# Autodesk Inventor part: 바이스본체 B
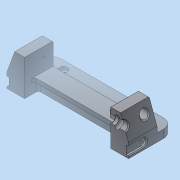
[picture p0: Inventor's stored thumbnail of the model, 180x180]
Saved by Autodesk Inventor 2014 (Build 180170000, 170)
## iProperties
Created: 2017-04
Part Number: 바이스본체 B
Material: 알루미늄 6061
Document SubType Name: Modeling
Designer: mduedu
Density: 2.71 g/cm^3
Appearance: 기본값
Mass: 324.113 g
Surface Area: 275.971 cm^2
Volume: 119.599 cm^3
Author: mduedu
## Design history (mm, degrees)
sketch "스케치1"
  geometry: L1 (-75, 0)-(75, 0); L2 (-75, 0)-(-75, 17); L3 (-53, 17)-(53, 17); L4 (75, 17)-(75, 0); L5 (-75, 17)-(-65.173, 44); L6 (-65.173, 44)-(-53, 44); L7 (-53, 44)-(-53, 17); L8 (0, 0)-(0, 17); L9 (75, 17)-(65.173, 44); L10 (65.173, 44)-(53, 44); L11 (53, 44)-(53, 17); 1 further point
  constraints: 22 end point, 4 perpendicular, 2 horizontal alignment, 2 midpoint, 2 symmetric about line, 1 coincident, 1 collinear, 1 horizontal, 1 vertical
  dimensions: "d0" = 150 distance of L1.start L1.end; "d1" = 17 distance of L1.start L2.end; "d2" = 27 distance of L3.start L6.end; "d3" = 22 distance of L3.start L2.end; "d4" = 70 deg angle of L3 L5; "d54" = 20 deg angle of L9 L4
extrude "돌출1" new body sketch "스케치1" stored distance "d5" = 70; taper "d6" = 0 deg
sketch "스케치2"
  geometry: L1 (0, 70)-(106, 70) reference; L2 (106, 70)-(106, 0) reference; L3 (106, 0)-(0, 0) reference; L4 (0, 47)-(106, 47); L5 (106, 47)-(106, 23); L6 (106, 23)-(0, 23); L7 (0, 23)-(0, 47); L8 (0, 70)-(0, 0) reference; 2 further points
  constraints: 8 end point, 2 parallel, 2 point on line, 1 horizontal, 1 horizontal alignment, 1 midpoint, 1 perpendicular
  dimensions: "d7" = 24 distance between parallel lines of L6 L4
extrude "돌출2" cut sketch "스케치2" stored distance "d9" = 70; taper "d10" = 0 deg
sketch "스케치3"
  geometry: L1 (22, -23)-(128, -23) reference; L2 (128, -47)-(22, -47) reference; L3 (22, -18)-(128, -18); L4 (128, -52)-(22, -52); L5 (22, -18)-(22, -52); L6 (128, -18)-(128, -52); 1 further point
  constraints: 8 end point, 3 parallel, 2 point on line, 1 perpendicular
  dimensions: "d11" = 5 distance between parallel lines of L3 L1; "d12" = 5 distance between parallel lines of L4 L2
extrude "돌출3" cut sketch "스케치3" distance "d13" = 12; taper "d14" = 0 deg
fillet "모깎기1" dims "d15" = 3, "d16" = 3
sketch "스케치4"
  geometry: L1 (103, 23)-(3, 23) reference; L2 (0, 26)-(0, 0) reference; L3 (106, 0)-(0, 0) reference; L4 (106, 26)-(106, 0) reference; L5 (96, 0)-(90, 0); L6 (90, 0)-(90, 19.5); L7 (96, 19.5)-(96, 0); L8 (90, 19.5)-(96, 19.5); A1 r 3 centre (3, 26) between (0, 26) and (3, 23) reference; A2 r 3 centre (103, 26) between (103, 23) and (106, 26) reference; 1 further point
  constraints: 8 end point, 2 perpendicular, 1 horizontal, 1 parallel, 1 point on line
  dimensions: "d17" = 10 distance between parallel lines of L7 L4; "d18" = 6 distance between parallel lines of L7 L6; "d27" = 3.5 distance between parallel lines of L8 L1
extrude "돌출4" join sketch "스케치4" distance "d19" = 12; taper "d20" = 0 deg
chamfer "모따기1" distance "d21" = 3; stored, may be unused: second distance "d22" = 2, angle "d23" = 45 deg
chamfer "모따기2" distance "d24" = 3; stored, may be unused: second distance "d25" = 2, angle "d26" = 45 deg
sketch "스케치5"
  geometry: L1 (-15.5, 35.8)-(-15.5, -25.8) reference; L2 (19.5, 0)-(0, 0) reference; C1 r 6.5 at (9.5, 15); 1 further point
  constraints: 1 centre point
  dimensions: "d28" = 13 diameter of C1; "d30" = 15 distance from line of C1.centre L2; "d31" = 25 distance from line of C1.centre L1
extrude "돌출5" cut sketch "스케치5" stored distance "d32" = 12; taper "d33" = 0 deg
sketch "스케치6"
  geometry: C1 r 5 at (-10, 15); C2 r 5 at (-60, 15); A1 r 6.5 centre (-10, 15) between (-15.766, 12) and (-4.234, 12) reference; A2 r 6.5 centre (-60, 15) between (-65.766, 12) and (-54.234, 12) reference; 1 further point
  constraints: 2 centre point, 2 coincident
  dimensions: "d34" = 10 diameter of C1; "d35" = 10 diameter of C2 (= d34)
extrude "돌출6" cut sketch "스케치6" stored distance "d36" = 12; taper "d37" = 0 deg
chamfer "모따기3" distance "d38" = 1; stored, may be unused: second distance "d39" = 2, angle "d40" = 45 deg
chamfer "모따기4" distance "d41" = 1; stored, may be unused: second distance "d42" = 2, angle "d43" = 45 deg
sketch "스케치7"
  geometry: L1 (-35, 35.8)-(-35, -25.8) reference; L2 (-70, 0)-(0, 0) reference; C1 r 5 at (-35, 15); 1 further point
  constraints: 1 centre point, 1 point on line
  dimensions: "d44" = 10 diameter of C1; "d45" = 15 distance from line of C1.centre L2
extrude "돌출7" cut sketch "스케치7" stored distance "d46" = 12; taper "d47" = 0 deg
chamfer "모따기5" distance "d48" = 1; stored, may be unused: second distance "d49" = 2, angle "d50" = 45 deg
node "작업축1"
sketch "스케치8"
  geometry: L1 (-105, 32)-(105, 32) reference; L2 (58, 32)-(64, 32); L3 (64, 32)-(64, 40); L4 (64, 40)-(58, 40); L5 (58, 40)-(58, 32); L6 (53, 38)-(53, 26) reference; 1 further point
  constraints: 8 end point, 2 parallel, 1 horizontal, 1 perpendicular, 1 point on line
  dimensions: "d51" = 5 distance from line of L6 L2.start; "d52" = 6 distance of L3.end L4.end; "d53" = 16 diameter of L4 L1
revolve "회전1" sketch "스케치8" stored, may be unused: angle "d55" = 90 deg
fillet "모깎기2"
chamfer "모따기6" distance "d56" = 1; stored, may be unused: second distance "d57" = 2, angle "d58" = 45 deg
sketch "스케치9"
  geometry: L1 (17.5, 3)-(52.5, 3); L2 (52.5, 13)-(17.5, 13); L3 (70, 0)-(0, 0) reference; L4 (17.5, 8)-(52.5, 8); A1 r 5 centre (17.5, 8) between (17.5, 13) and (17.5, 3); A2 r 5 centre (52.5, 8) between (52.5, 3) and (52.5, 13); 3 further points
  constraints: 6 end point, 4 point on circle, 3 tangent, 2 centre point, 2 midpoint, 2 parallel, 1 horizontal, 1 vertical alignment
  dimensions: "d59" = 35 distance of L4.start L4.end; "d61" = 5 radius of A2; "d62" = 8 distance between parallel lines of L3 L4
extrude "돌출8" cut sketch "스케치9" distance "d63" = 3; taper "d64" = 0 deg
chamfer "모따기7" distance "d65" = 1; stored, may be unused: second distance "d66" = 2, angle "d67" = 45 deg
chamfer "모따기8" distance "d68" = 1; stored, may be unused: second distance "d69" = 2, angle "d70" = 45 deg
feature "분할1"
sketch "스케치10"
  geometry: A1 r 5 centre (0, 0) between (0, 5) and (0, -5) reference; 1 further point
  constraints: 1 coincident
hole "구멍1" sketch "스케치10" at (0, 0) diameter "d71" = 2.459; stored, may be unused: countersink angle "d75" = 90 deg, drill point angle "d77" = 120 deg; dims "d72" = 4.5, "d73" = 4, "d74" = 2, "d76" = 6
sketch "스케치11"
  geometry: L1 (0, 0)-(0, 27) reference; L2 (0, 27)-(-35, 27) reference; 2 further points
  dimensions: "d78" = 12 distance from line of point (-12, 15.5) L1; "d79" = 11.5 distance from line of point (-12, 15.5) L2
hole "구멍2" sketch "스케치11" at (-12, 15.5) diameter "d80" = 3.242; stored, may be unused: countersink angle "d84" = 90 deg, drill point angle "d86" = 120 deg; dims "d81" = 8, "d82" = 4, "d83" = 2, "d85" = 10
sketch "스케치12"
  geometry: L1 (-75, -35)-(-75, 0) reference; L2 (75, -35)-(75, 0) reference; L3 (75, -35)-(-75, -35); L4 (-75, -35)-(-75, -55); L5 (-75, -55)-(75, -55); L6 (75, -55)-(75, -35); 1 further point
  constraints: 8 end point, 2 parallel, 1 horizontal, 1 perpendicular, 1 point on line
  dimensions: "d87" = 20 distance of L3.end L4.end; "d89" = 150 distance of L4.end L5.end (derived)
extrude "돌출9" join sketch "스케치12" distance "d90" = 10; taper "d91" = 0 deg
sketch "스케치13"
  geometry: L1 (-75, 55)-(-75, 35) reference; L2 (75, 35)-(75, 55) reference; L3 (-75, 45)-(75, 45); 3 further points
  constraints: 2 end point, 2 midpoint, 2 point on line
  dimensions: "d92" = 50 horizontal distance of point (-50, 45) point (0, 0); "d93" = 100 distance of point (50, 45) point (-50, 45)
fillet "모깎기3" dims "d94" = 12
chamfer "모따기9" distance "d95" = 1; stored, may be unused: second distance "d96" = 2, angle "d97" = 45 deg
hole "구멍3" sketch "스케치13" diameter "d98" = 4.134; stored, may be unused: countersink angle "d102" = 90 deg, drill point angle "d104" = 118 deg; dims "d99" = 6, "d100" = 10, "d101" = 4, "d103" = 8
node "솔리드1"
mirror "대칭1"
mirror "대칭2"
mirror "대칭3"
mirror "대칭4"
node "투영된 루프1"
